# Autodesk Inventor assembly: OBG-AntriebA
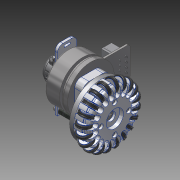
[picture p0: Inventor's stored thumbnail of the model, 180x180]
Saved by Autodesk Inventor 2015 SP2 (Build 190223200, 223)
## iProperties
Created: 2012-07
Part Number: OBG-AntriebA
Document SubType Name: Assembly
Designer: rYan
Mass: 389.044 g
Surface Area: 554.19 cm^2
Volume: 67.7043 cm^3
Density: 5.74622 g/cm^3
Author: rYan
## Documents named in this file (12)
- D:\TIGERs GIT\Hardware\mechanik\2016\Inventor\Antrieb\OBG-AntriebA.iam
- D:\TIGERs GIT\Hardware\mechanik\2016\Inventor\Antrieb\UBG-Rad.iam
- D:\TIGERs GIT\Hardware\mechanik\2016\Inventor\Inhaltscenter\de-DE\DIN 7984\DIN 7984 - M3 x 8.ipt
- D:\TIGERs GIT\Hardware\mechanik\2016\Inventor\Antrieb\Lagerbock.ipt
- D:\TIGERs GIT\Hardware\mechanik\2016\Inventor\Kaufteile\MG-MaxonEC45-50W.iam
- D:\TIGERs GIT\Hardware\mechanik\2016\Inventor\Kaufteile\Abstandsbolzen Typ B M2.5-22mm.ipt
- D:\Tigers SVN\mechanik\2016\Inventor\Kaufteile\Abstandsbolzen Typ B.ipt
- D:\TIGERs GIT\Hardware\mechanik\2016\Inventor\Antrieb\Encoderhalter.ipt
- D:\TIGERs GIT\Hardware\mechanik\2016\Inventor\Inhaltscenter\de-DE\ISO 4762(1)\ISO 4762 - M2,5 x 6DIN EN ISO.ipt
- D:\TIGERs GIT\Hardware\mechanik\2016\Inventor\Kaufteile\E8P-X-157-S-D-M-X\E8P-X-157-S-D-M-X.iam
- D:\TIGERs GIT\Hardware\mechanik\2016\Inventor\Kaufteile\Ritzel z18.ipt
- D:\TIGERs GIT\Hardware\mechanik\2016\Inventor\Kaufteile\E4T-X-157-S-D-M-X\E4T-X-157-S-D-M-X.iam
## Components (16 placed, 10 different names)
1. Lagerbock:1 — Passend:3, Passend:16, Passend:17, Passend:19, Passend:20, Passend:21, Winkel:1, Passend:23, Passend:24, Passend:25, Passend:26
2. MG-MaxonEC45-50W:1 [sub-assembly] — Passend:3, Passend:20, Passend:21, Passend:41, Passend:42
3. Ritzel z=18:1 — Passend:41, Passend:42
4. UBG-Rad:1 [sub-assembly] — Passend:16, Passend:17, Winkel:1
5. Abstandsbolzen Typ B M2.5-22mm:1 — Passend:24, Passend:26, Passend:28
6. Abstandsbolzen Typ B M2.5-22mm:2 — Passend:23, Passend:25, Passend:27, Passend:29
7. Encoderhalter:1 — Passend:27, Passend:28, Passend:29, Passend:31, Passend:33, Passend:34, Passend:35, Passend:36, Passend:37, Passend:38, Einfügen:1, Winkel:2
8. DIN EN ISO 4762 M2,5 x 6:1 — Passend:31
9. DIN EN ISO 4762 M2,5 x 6:2 — Passend:33
10. E8P-X-157-S-D-M-X:1 [sub-assembly] — Passend:34, Passend:35, Passend:36, Passend:39, Passend:40
11. DIN EN ISO 4762 M2,5 x 6:3 — Passend:38, Passend:40
12. DIN EN ISO 4762 M2,5 x 6:4 — Passend:37, Passend:39
13. E4T-X-157-S-D-M-X:1 [sub-assembly] — Einfügen:1, Winkel:2
14. DIN 7984 M3 x 8:1 — Passend:19
15. DIN 7984 M3 x 8:2
16. DIN 7984 M3 x 8:3
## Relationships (27: Mate 24, Angle 2, Insert 1)
- Passend:3 [Mate]: Lagerbock:1 ↔ MG-MaxonEC45-50W:1
- Passend:16 [Mate]: Lagerbock:1 ↔ UBG-Rad:1
- Passend:17 [Mate]: Lagerbock:1 ↔ UBG-Rad:1
- Passend:19 [Mate]: Lagerbock:1 ↔ DIN 7984 M3 x 8:1
- Passend:20 [Mate]: Lagerbock:1 ↔ MG-MaxonEC45-50W:1
- Passend:21 [Mate]: Lagerbock:1 ↔ MG-MaxonEC45-50W:1
- Winkel:1 [Angle]: Lagerbock:1 ↔ UBG-Rad:1
- Passend:23 [Mate]: Lagerbock:1 ↔ Abstandsbolzen Typ B M2.5-22mm:2
- Passend:24 [Mate]: Lagerbock:1 ↔ Abstandsbolzen Typ B M2.5-22mm:1
- Passend:25 [Mate]: Lagerbock:1 ↔ Abstandsbolzen Typ B M2.5-22mm:2
- Passend:26 [Mate]: Lagerbock:1 ↔ Abstandsbolzen Typ B M2.5-22mm:1
- Passend:27 [Mate]: Abstandsbolzen Typ B M2.5-22mm:2 ↔ Encoderhalter:1
- Passend:28 [Mate]: Abstandsbolzen Typ B M2.5-22mm:1 ↔ Encoderhalter:1
- Passend:29 [Mate]: Abstandsbolzen Typ B M2.5-22mm:2 ↔ Encoderhalter:1
- Passend:31 [Mate]: Encoderhalter:1 ↔ DIN EN ISO 4762 M2,5 x 6:1
- Passend:33 [Mate]: Encoderhalter:1 ↔ DIN EN ISO 4762 M2,5 x 6:2
- Passend:34 [Mate]: Encoderhalter:1 ↔ E8P-X-157-S-D-M-X:1
- Passend:35 [Mate]: Encoderhalter:1 ↔ E8P-X-157-S-D-M-X:1
- Passend:36 [Mate]: Encoderhalter:1 ↔ E8P-X-157-S-D-M-X:1
- Passend:37 [Mate]: Encoderhalter:1 ↔ DIN EN ISO 4762 M2,5 x 6:4
- Passend:38 [Mate]: Encoderhalter:1 ↔ DIN EN ISO 4762 M2,5 x 6:3
- Passend:39 [Mate]: E8P-X-157-S-D-M-X:1 ↔ DIN EN ISO 4762 M2,5 x 6:4
- Passend:40 [Mate]: E8P-X-157-S-D-M-X:1 ↔ DIN EN ISO 4762 M2,5 x 6:3
- Passend:41 [Mate]: MG-MaxonEC45-50W:1 ↔ Ritzel z=18:1
- Passend:42 [Mate]: MG-MaxonEC45-50W:1 ↔ Ritzel z=18:1
- Einfügen:1 [Insert]: Encoderhalter:1 ↔ E4T-X-157-S-D-M-X:1
- Winkel:2 [Angle]: Encoderhalter:1 ↔ E4T-X-157-S-D-M-X:1
